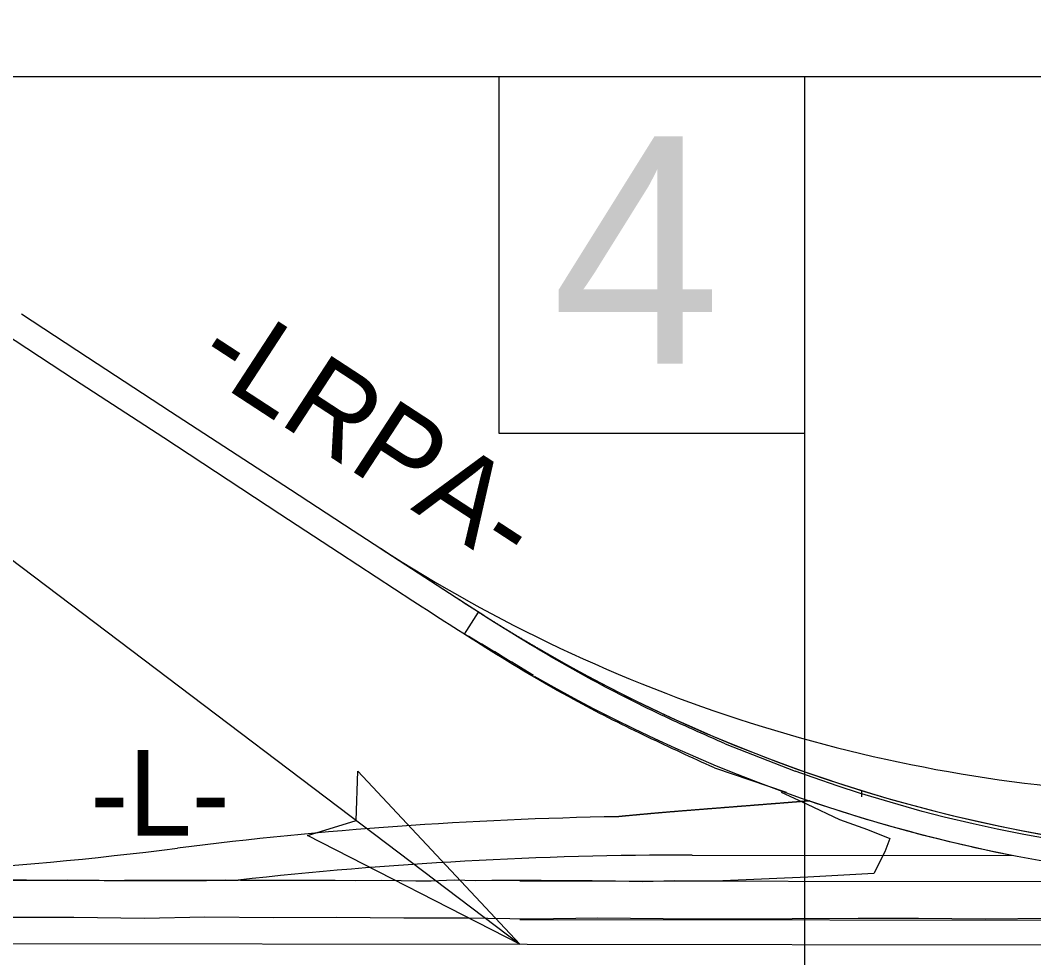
# Model space of a CAD drawing. Extents: x 2241278 to 2254132, y 649924 to 670434.
# Drawn here: x 2248087 to 2248712, y 663043 to 663620 of the extents above; entities that cross this region are included whole.
import ezdxf

# ---------------------------------------------------------------- set-up
doc = ezdxf.new("R2010")
doc.units = 0
for name, color, linetype in [('Pattern 4', 7, 'Continuous'), ('Prop DSN Text', 7, 'Continuous'), ('Prop Horizontal Alignment', 7, 'Continuous'), ('Prop RDY Alternate Text Yellow', 7, 'Continuous'), ('Prop Shade Heavy', 7, 'Continuous'), ('Prop Terminator CELL', 7, 'Continuous')]:
    doc.layers.add(name, color=color, linetype=linetype)

msp = doc.modelspace()

# ---------------------------------------------------------------- linework, layer by layer
at = {"layer": 'Pattern 4'}
for p, q in [((2248521.841407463, 663174.6436971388), (2248519.522645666, 663175.6435080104)), ((2248515.105036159, 663159.9058468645), (2248512.2885336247, 663161.0440069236)), ((2248515.105036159, 663159.9058468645), (2248559.4573341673, 663144.8071298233)), ((2248572.6726083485, 663092.3894687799), (2248520.317586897, 663090.174365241))]:
    msp.add_line(p, q, dxfattribs=at)
for points in [[(2248329.4042654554, 663262.4849119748), (2248284.103792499, 663292.0088999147), (2248247.485026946, 663316.0393573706), (2248175.8289858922, 663363.1105922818), (2248120.94965518, 663398.9078180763), (2248069.69245421, 663432.3596387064), (2248013.455276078, 663469.3554114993)], [(2248356.078308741, 663264.522525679), (2248292.577075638, 663305.7805350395), (2248253.8827733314, 663331.0648143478), (2248180.027896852, 663379.1161574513), (2248128.9810908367, 663412.5338641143), (2248088.157115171, 663439.3493886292)], [(2248521.841407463, 663174.6436971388), (2248565.005607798, 663157.6808520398)], [(2248721.7288937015, 663115.7938782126), (2248705.705206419, 663118.8617455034), (2248689.3392274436, 663122.0928519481), (2248674.518223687, 663125.3018916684), (2248656.802756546, 663129.4215805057), (2248643.099353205, 663133.0088348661), (2248623.461257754, 663138.6610662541), (2248604.4928478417, 663144.2158653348), (2248591.409358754, 663148.6315901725), (2248576.069985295, 663153.8869197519), (2248565.005607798, 663157.6808520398)], [(2248556.2431529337, 663144.7862920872), (2248572.2395090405, 663137.4677206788), (2248592.2424454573, 663128.0480086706), (2248609.576193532, 663121.8171947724), (2248623.3003326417, 663116.2153347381), (2248620.1638664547, 663108.031399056), (2248613.480428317, 663094.73850328), (2248572.6726083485, 663092.3894687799)], [(2248520.3169558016, 663090.1505896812), (2248504.1699949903, 663090.0648280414), (2248490.258087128, 663090.1531287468), (2248471.097404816, 663089.5668385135), (2248454.167620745, 663090.0858575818), (2248439.8441622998, 663090.1856504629), (2248424.9840950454, 663090.16302352), (2248408.3553073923, 663090.3644364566), (2248393.7272288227, 663090.4104906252), (2248377.930521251, 663090.3922780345), (2248367.899822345, 663090.2218880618), (2248354.894198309, 663090.6701577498), (2248340.5607366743, 663090.0924431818), (2248331.202885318, 663090.1106841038), (2248322.2477210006, 663090.1817673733), (2248310.2437386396, 663090.4806928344), (2248293.9882655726, 663090.1757451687), (2248281.4074375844, 663090.3535317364), (2248266.2599229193, 663090.4915979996), (2248254.554710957, 663090.4936267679), (2248239.906586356, 663090.3800321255), (2248223.15478609, 663090.4814798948), (2248213.939390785, 663090.5687101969), (2248202.102689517, 663090.479697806), (2248189.8201901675, 663090.3666204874), (2248177.578149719, 663090.4348081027), (2248162.4825770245, 663090.515426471), (2248151.6016491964, 663090.5274904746), (2248144.5116996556, 663090.3141685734), (2248135.989562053, 663090.5297860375), (2248128.1249061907, 663090.369108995), (2248116.7527300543, 663090.5500134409), (2248104.26732042, 663090.4141996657), (2248091.341284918, 663090.5368274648), (2248076.6107930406, 663090.6756517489)], [(2248081.0464070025, 663067.8691718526), (2248120.515788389, 663067.793861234), (2248163.942384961, 663067.1577460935), (2248201.1825565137, 663068.1425949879), (2248243.7835089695, 663067.6533045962), (2248282.20537548, 663067.7618854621), (2248323.7761026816, 663067.4963602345), (2248362.271043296, 663067.3567569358), (2248402.4895016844, 663066.8427278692), (2248443.2896640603, 663067.5144587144), (2248483.63697068, 663066.9709829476), (2248520.1972854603, 663066.8292124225), (2248562.9629134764, 663067.0011915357), (2248603.7788076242, 663067.1774478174), (2248640.827062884, 663067.1459457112), (2248681.9061098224, 663066.8638399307), (2248721.980150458, 663067.1694241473)]]:
    msp.add_lwpolyline(points, dxfattribs=at)
for points in [[(2248512.2885336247, 663161.0440069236), (2248471.59970113, 663180.0010341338), (2248428.6155889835, 663201.8366734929), (2248374.250741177, 663233.8227666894), (2248329.4042654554, 663262.4849119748)], [(2248519.522645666, 663175.6435080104), (2248479.68988319, 663193.7265774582), (2248434.573521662, 663216.8895753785), (2248382.2923462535, 663247.744846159), (2248356.078308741, 663264.522525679)]]:
    msp.add_spline(points, degree=3, dxfattribs=at)
at = {"layer": 'Prop DSN Text'}
for p, q in [((2251198.4216737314, 663585.5258229), (2247330.488405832, 663585.4218419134)), ((2248382.4794424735, 663365.7874708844), (2248382.479873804, 663585.4501224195)), ((2248570.7292612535, 663585.4551830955), (2248570.7574885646, 662535.4424933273)), ((2248570.7351665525, 663365.7871012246), (2248382.4794424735, 663365.7874708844)), ((2248361.085718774, 663242.2367312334), (2248369.7734972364, 663255.7572342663)), ((2248395.317459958, 663090.2059901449), (2248825.5682528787, 663089.6958861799))]:
    msp.add_line(p, q, dxfattribs=at)
msp.add_lwpolyline([(2249158.8155779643, 663065.3007723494), (2248395.289052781, 663066.2060069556)], dxfattribs=at)
for centre, radius, start, end in [((2248884.8876708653, 664051.8690549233), 948.0000000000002, 240.0836274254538, 267.63207033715), ((2248884.887670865, 664051.8690549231), 963.9999999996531, 240.08637361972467, 266.4720945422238)]:
    msp.add_arc(centre, radius, start, end, dxfattribs=at)
for points in [[(2248369.7734972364, 663255.7572342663), (2248370.8998162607, 663255.0369322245), (2248371.4631196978, 663254.677528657), (2248372.0266744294, 663254.3185233), (2248372.5904801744, 663253.9599163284), (2248373.154536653, 663253.601707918), (2248373.71884358, 663253.2438982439), (2248374.283400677, 663252.8864874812), (2248374.84820766, 663252.529475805), (2248375.413264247, 663252.1728633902), (2248375.978570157, 663251.8166504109), (2248376.544125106, 663251.4608370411), (2248377.109928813, 663251.1054234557), (2248377.675980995, 663250.7504098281), (2248378.2422813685, 663250.3957963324), (2248378.8088296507, 663250.0415831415), (2248379.3756255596, 663249.6877704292), (2248379.942668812, 663249.3343583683), (2248380.5099591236, 663248.9813471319), (2248381.077496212, 663248.6287368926), (2248381.6452797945, 663248.2765278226), (2248382.213309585, 663247.9247200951), (2248382.7815853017, 663247.5733138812), (2248383.350106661, 663247.2223093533), (2248383.918873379, 663246.871706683), (2248384.4878851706, 663246.521506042), (2248385.0571417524, 663246.171707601), (2248385.6266428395, 663245.8223115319), (2248386.1963881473, 663245.4733180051), (2248386.7663773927, 663245.1247271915), (2248387.3366102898, 663244.7765392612), (2248387.907086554, 663244.4287543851), (2248388.4778059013, 663244.0813727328), (2248389.0487680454, 663243.7343944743), (2248389.619972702, 663243.3878197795), (2248390.1914195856, 663243.0416488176), (2248390.7631084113, 663242.695881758), (2248391.335038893, 663242.3505187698), (2248391.907210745, 663242.0055600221), (2248392.479623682, 663241.6610056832), (2248393.052277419, 663241.3168559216), (2248393.6251716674, 663240.9731109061), (2248394.198306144, 663240.6297708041), (2248394.7716805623, 663240.2868357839), (2248395.345294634, 663239.9443060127), (2248395.9191480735, 663239.6021816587), (2248396.493240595, 663239.2604628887), (2248397.0675719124, 663238.9191498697), (2248397.642141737, 663238.5782427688), (2248398.216949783, 663238.2377417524), (2248398.791995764, 663237.8976469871), (2248399.3672793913, 663237.5579586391), (2248399.9428003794, 663237.2186768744), (2248400.5185584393, 663236.8798018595), (2248401.0945532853, 663236.5413337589), (2248401.670784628, 663236.2032727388), (2248402.247252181, 663235.8656189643), (2248402.8239556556, 663235.5283726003), (2248403.400894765, 663235.1915338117), (2248403.97806922, 663234.8551027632), (2248404.5554787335, 663234.519079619), (2248405.133123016, 663234.1834645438), (2248405.7110017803, 663233.8482577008), (2248406.289114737, 663233.5134592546), (2248406.867461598, 663233.1790693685), (2248407.4460420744, 663232.8450882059), (2248408.024855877, 663232.51151593), (2248408.6039027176, 663232.1783527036), (2248409.1831823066, 663231.8455986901), (2248409.7626943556, 663231.5132540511), (2248410.342438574, 663231.1813189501), (2248410.922414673, 663230.8497935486), (2248411.502622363, 663230.5186780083), (2248412.0830613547, 663230.1879724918)], [(2248403.624825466, 663216.6585334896), (2248403.6147998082, 663216.6632669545), (2248403.5848223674, 663216.6808397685), (2248361.085718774, 663242.2367312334)]]:
    msp.add_spline(points, degree=3, dxfattribs=at)
at = {"layer": 'Prop Horizontal Alignment'}
msp.add_line((2247428.233538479, 663052.3525343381), (2250137.966660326, 663049.1398834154), dxfattribs=at)
at = {"layer": 'Prop RDY Alternate Text Yellow'}
msp.add_line((2247642.6348494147, 663620.3536490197), (2248395.271298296, 663051.206017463), dxfattribs=at)
at = {"layer": 'Prop Shade Heavy'}
for p, q in [((2248605.912653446, 663141.9565136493), (2248605.9173879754, 663145.9565108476)), ((2248501.525676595, 663106.0800443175), (2248699.588879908, 663105.8456101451)), ((2248139.1278161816, 663090.4503854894), (2248139.128363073, 663090.5097271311))]:
    msp.add_line(p, q, dxfattribs=at)
for points in [[(2248369.7734972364, 663255.7572342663), (2248356.078308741, 663264.522525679), (2248309.2690039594, 663294.9354584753), (2248309.380721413, 663295.1012735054)], [(2247870.317827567, 663090.8271516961), (2247955.5535505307, 663090.7952202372), (2248023.034450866, 663090.5553697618), (2248139.1278161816, 663090.4503854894)], [(2248139.128363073, 663090.5097271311), (2248139.1278161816, 663090.4503854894), (2248189.8201901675, 663090.3666204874), (2248202.102689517, 663090.479697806), (2248221.6983625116, 663090.6270579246)]]:
    msp.add_lwpolyline(points, dxfattribs=at)
for centre, radius, start, end in [((2248824.332909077, 664091.0461487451), 947.9999999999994, 237.09835811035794, 267.63207033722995), ((2248884.8876708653, 664051.8690549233), 948.0000000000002, 240.0836274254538, 266.4430096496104), ((2248884.887670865, 664051.8690549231), 963.9999999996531, 251.17603514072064, 258.91770877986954), ((2248498.5807993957, 660618.0817890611), 2511.9999980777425, 90.97857068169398, 97.18442970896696), ((2247873.262704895, 665578.8254088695), 2487.9999999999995, 269.93218284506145, 277.1844297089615), ((2248498.5807993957, 660618.0817890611), 2487.999998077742, 89.93218284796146, 96.38951962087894)]:
    msp.add_arc(centre, radius, start, end, dxfattribs=at)
for points in [[(2248412.0830613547, 663230.1879724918), (2248411.502622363, 663230.5186780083), (2248410.922414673, 663230.8497935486), (2248410.342438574, 663231.1813189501), (2248409.7626943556, 663231.5132540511), (2248409.1831823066, 663231.8455986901), (2248408.6039027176, 663232.1783527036), (2248408.024855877, 663232.51151593), (2248407.4460420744, 663232.8450882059), (2248406.867461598, 663233.1790693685), (2248406.289114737, 663233.5134592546), (2248405.7110017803, 663233.8482577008), (2248405.133123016, 663234.1834645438), (2248404.5554787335, 663234.519079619), (2248403.97806922, 663234.8551027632), (2248403.400894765, 663235.1915338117), (2248402.8239556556, 663235.5283726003), (2248402.247252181, 663235.8656189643), (2248401.670784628, 663236.2032727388), (2248401.0945532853, 663236.5413337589), (2248400.5185584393, 663236.8798018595), (2248399.9428003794, 663237.2186768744), (2248399.3672793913, 663237.5579586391), (2248398.791995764, 663237.8976469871), (2248398.216949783, 663238.2377417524), (2248397.642141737, 663238.5782427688), (2248397.0675719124, 663238.9191498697), (2248396.493240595, 663239.2604628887), (2248395.9191480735, 663239.6021816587), (2248395.345294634, 663239.9443060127), (2248394.7716805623, 663240.2868357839), (2248394.198306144, 663240.6297708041), (2248393.6251716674, 663240.9731109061), (2248393.052277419, 663241.3168559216), (2248392.479623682, 663241.6610056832), (2248391.907210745, 663242.0055600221), (2248391.335038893, 663242.3505187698), (2248390.7631084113, 663242.695881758), (2248390.1914195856, 663243.0416488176), (2248389.619972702, 663243.3878197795), (2248389.0487680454, 663243.7343944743), (2248388.4778059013, 663244.0813727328), (2248387.907086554, 663244.4287543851), (2248387.3366102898, 663244.7765392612), (2248386.7663773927, 663245.1247271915), (2248386.1963881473, 663245.4733180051), (2248385.6266428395, 663245.8223115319), (2248385.0571417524, 663246.171707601), (2248384.4878851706, 663246.521506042), (2248383.918873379, 663246.871706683), (2248383.350106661, 663247.2223093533), (2248382.7815853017, 663247.5733138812), (2248382.213309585, 663247.9247200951), (2248381.6452797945, 663248.2765278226), (2248381.077496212, 663248.6287368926), (2248380.5099591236, 663248.9813471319), (2248379.942668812, 663249.3343583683), (2248379.3756255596, 663249.6877704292), (2248378.8088296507, 663250.0415831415), (2248378.2422813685, 663250.3957963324), (2248377.675980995, 663250.7504098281), (2248377.109928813, 663251.1054234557), (2248376.544125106, 663251.4608370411), (2248375.978570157, 663251.8166504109), (2248375.413264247, 663252.1728633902), (2248374.84820766, 663252.529475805), (2248374.283400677, 663252.8864874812), (2248373.71884358, 663253.2438982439), (2248373.154536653, 663253.601707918), (2248372.5904801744, 663253.9599163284), (2248372.0266744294, 663254.3185233), (2248371.4631196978, 663254.677528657), (2248370.8998162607, 663255.0369322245), (2248369.7734972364, 663255.7572342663)], [(2248555.906232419, 663138.015700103), (2248555.2304932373, 663137.9624458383), (2248554.554754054, 663137.9091915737), (2248553.879014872, 663137.8559373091), (2248553.2032756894, 663137.8026830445), (2248552.5275365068, 663137.7494287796), (2248551.8517973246, 663137.6961745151), (2248551.1760581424, 663137.6429202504), (2248550.5003189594, 663137.5896659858), (2248549.824579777, 663137.5364117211), (2248549.1488405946, 663137.4831574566), (2248548.473101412, 663137.429903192), (2248547.79736223, 663137.3766489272), (2248547.1216230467, 663137.3233946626), (2248546.4458838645, 663137.2701403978), (2248545.770144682, 663137.2168861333), (2248545.0944054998, 663137.1636318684), (2248544.418666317, 663137.1103776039), (2248543.7429271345, 663137.0571233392), (2248543.067187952, 663137.0038690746), (2248542.3914487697, 663136.95061481), (2248541.715709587, 663136.8973605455), (2248541.039970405, 663136.8441062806), (2248540.3642312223, 663136.7908520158), (2248539.688492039, 663136.7375977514), (2248539.012752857, 663136.6843434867), (2248538.3370136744, 663136.6310892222), (2248537.6612744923, 663136.5778349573), (2248536.9855353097, 663136.5245806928), (2248536.3097961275, 663136.471326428), (2248535.6340569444, 663136.4180721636), (2248534.958317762, 663136.3648178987), (2248534.28257858, 663136.3115636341), (2248533.6068393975, 663136.2583093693), (2248532.931100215, 663136.205055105), (2248532.2553610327, 663136.1518008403), (2248531.5796218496, 663136.0985465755), (2248530.903882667, 663136.045292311), (2248530.228143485, 663135.9920380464), (2248529.5524043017, 663135.938783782), (2248528.876665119, 663135.8855295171), (2248528.200925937, 663135.8322752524), (2248527.5251867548, 663135.7790209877), (2248526.8494475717, 663135.7257667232), (2248526.17370839, 663135.6725124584), (2248525.497969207, 663135.6192581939), (2248524.8222300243, 663135.5660039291), (2248524.146490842, 663135.5127496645), (2248523.47075166, 663135.4594953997), (2248522.795012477, 663135.4062411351), (2248522.1192732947, 663135.3529868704), (2248521.443534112, 663135.2997326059), (2248520.7677949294, 663135.2464783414), (2248520.0920557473, 663135.1932240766), (2248519.4163165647, 663135.139969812), (2248518.740577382, 663135.0867155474), (2248518.0648381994, 663135.0334612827), (2248517.3890990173, 663134.9802070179), (2248516.7133598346, 663134.9269527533), (2248516.0376206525, 663134.8736984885), (2248515.36188147, 663134.8204442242), (2248514.686142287, 663134.7671899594), (2248514.010403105, 663134.7139356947), (2248513.3346639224, 663134.6606814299), (2248512.65892474, 663134.6074271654), (2248511.983185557, 663134.5541729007), (2248511.3074463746, 663134.5009186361), (2248510.6317071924, 663134.4476643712), (2248509.95596801, 663134.3944101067), (2248509.280228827, 663134.3411558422), (2248508.604489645, 663134.2879015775), (2248507.928750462, 663134.2346473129), (2248507.2530112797, 663134.1813930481), (2248506.577272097, 663134.1281387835), (2248505.901532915, 663134.0748845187)], [(2248505.901532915, 663134.0748845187), (2248505.2257937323, 663134.0216302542), (2248504.5500545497, 663133.9683759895), (2248503.874315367, 663133.9151217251), (2248503.1985761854, 663133.8618674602), (2248502.5228370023, 663133.8086131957), (2248501.8470978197, 663133.755358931), (2248501.1689403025, 663133.7020773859), (2248500.489001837, 663133.6486309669), (2248499.8090924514, 663133.5950007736), (2248499.129212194, 663133.5411868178), (2248498.4493611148, 663133.4871891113), (2248497.7695392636, 663133.4330076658), (2248497.0897466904, 663133.3786424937), (2248496.4099834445, 663133.3240936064), (2248495.730249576, 663133.2693610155), (2248495.050545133, 663133.2144447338), (2248494.370870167, 663133.1593447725), (2248493.691224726, 663133.1040611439), (2248493.0116088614, 663133.0485938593), (2248492.3320226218, 663132.9929429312), (2248491.652466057, 663132.9371083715), (2248490.9729392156, 663132.8810901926), (2248490.2934421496, 663132.8248884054), (2248489.6139749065, 663132.7685030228), (2248488.934537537, 663132.7119340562), (2248488.2551300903, 663132.6551815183), (2248487.575752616, 663132.5982454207), (2248486.8964051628, 663132.5411257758), (2248486.2170877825, 663132.483822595), (2248485.5378005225, 663132.4263358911), (2248484.8585434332, 663132.3686656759), (2248484.1793165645, 663132.3108119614), (2248483.500119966, 663132.2527747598), (2248482.8209536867, 663132.1945540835), (2248482.141817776, 663132.1361499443), (2248481.462712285, 663132.0775623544), (2248480.783637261, 663132.0187913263), (2248480.1045927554, 663131.9598368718), (2248479.425578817, 663131.9006990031), (2248478.746595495, 663131.8413777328), (2248478.067642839, 663131.7818730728), (2248477.3887209, 663131.7221850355), (2248476.7098297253, 663131.6623136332), (2248476.030969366, 663131.6022588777), (2248475.3521398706, 663131.5420207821), (2248474.6733412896, 663131.4815993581), (2248473.994573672, 663131.4209946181), (2248473.315837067, 663131.3602065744), (2248472.637131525, 663131.2992352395), (2248471.9584570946, 663131.2380806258), (2248471.279813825, 663131.1767427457), (2248470.6012017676, 663131.1152216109), (2248469.9226209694, 663131.0535172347), (2248469.2440714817, 663130.9916296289), (2248468.565553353, 663130.9295588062), (2248467.887066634, 663130.8673047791), (2248467.2086113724, 663130.8048675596), (2248466.530187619, 663130.7422471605), (2248465.8517954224, 663130.6794435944), (2248465.1734348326, 663130.6164568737), (2248464.495105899, 663130.5532870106), (2248463.8168086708, 663130.489934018), (2248463.138543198, 663130.4263979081), (2248462.460309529, 663130.3626786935), (2248461.782107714, 663130.298776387), (2248461.103937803, 663130.2346910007), (2248460.425799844, 663130.1704225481), (2248459.7476938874, 663130.1059710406), (2248459.069619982, 663130.0413364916), (2248458.3915781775, 663129.9765189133), (2248457.713568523, 663129.9115183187), (2248457.035591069, 663129.84633472), (2248456.357645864, 663129.7809681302), (2248455.679732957, 663129.7154185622)]]:
    msp.add_spline(points, degree=3, dxfattribs=at)
msp.add_open_spline([(2248573.8418711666, 663139.429188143), (2248573.719731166, 663139.4195624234), (2248573.5975911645, 663139.4099367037), (2248573.475451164, 663139.400310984), (2248573.2502047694, 663139.3825595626), (2248573.0249583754, 663139.3648081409), (2248572.7997119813, 663139.3470567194), (2248572.5744655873, 663139.3293052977), (2248572.3492191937, 663139.3115538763), (2248572.123972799, 663139.2938024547), (2248571.898726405, 663139.2760510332), (2248571.673480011, 663139.2582996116), (2248571.448233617, 663139.24054819), (2248571.222987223, 663139.2227967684), (2248570.997740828, 663139.205045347), (2248570.772494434, 663139.1872939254), (2248570.54724804, 663139.1695425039), (2248570.322001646, 663139.1517910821), (2248570.0967552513, 663139.1340396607), (2248569.8715088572, 663139.1162882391), (2248569.646262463, 663139.0985368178), (2248569.421016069, 663139.0807853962), (2248569.1957696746, 663139.0630339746), (2248568.970523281, 663139.0452825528), (2248568.745276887, 663139.0275311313), (2248568.520030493, 663139.0097797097), (2248568.294784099, 663138.9920282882), (2248568.069537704, 663138.9742768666), (2248567.84429131, 663138.9565254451), (2248567.619044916, 663138.9387740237), (2248567.3937985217, 663138.9210226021), (2248567.168552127, 663138.9032711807), (2248566.943305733, 663138.8855197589), (2248566.718059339, 663138.8677683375), (2248566.492812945, 663138.850016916), (2248566.267566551, 663138.8322654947), (2248566.042320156, 663138.8145140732), (2248565.8170737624, 663138.7967626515), (2248565.5918273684, 663138.7790112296), (2248565.366580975, 663138.7612598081), (2248565.14133458, 663138.7435083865), (2248564.9160881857, 663138.7257569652), (2248564.6908417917, 663138.7080055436), (2248564.4655953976, 663138.690254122), (2248564.2403490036, 663138.6725027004), (2248564.015102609, 663138.6547512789), (2248563.789856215, 663138.6369998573), (2248563.564609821, 663138.6192484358), (2248563.339363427, 663138.6014970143), (2248563.1141170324, 663138.5837455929), (2248562.8888706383, 663138.5659941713), (2248562.6636242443, 663138.5482427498), (2248562.43837785, 663138.530491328), (2248562.213131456, 663138.5127399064), (2248561.9878850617, 663138.4949884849), (2248561.7626386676, 663138.4772370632), (2248561.5373922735, 663138.4594856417), (2248561.31214588, 663138.4417342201), (2248561.086899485, 663138.4239827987), (2248560.861653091, 663138.4062313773), (2248560.636406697, 663138.3884799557), (2248560.411160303, 663138.3707285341), (2248560.1859139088, 663138.3529771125), (2248559.9606675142, 663138.335225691), (2248559.73542112, 663138.3174742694), (2248559.510174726, 663138.2997228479), (2248559.2849283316, 663138.2819714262), (2248559.059681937, 663138.2642200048), (2248558.8344355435, 663138.2464685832), (2248558.6091891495, 663138.2287171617), (2248558.3839427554, 663138.2109657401), (2248558.158696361, 663138.1932143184), (2248557.933449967, 663138.1754628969), (2248557.708203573, 663138.1577114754), (2248557.4829571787, 663138.139960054), (2248557.257710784, 663138.1222086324), (2248557.0324643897, 663138.1044572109), (2248556.8072179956, 663138.0867057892), (2248556.581971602, 663138.0689543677), (2248556.3567252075, 663138.0512029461), (2248556.131478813, 663138.0334515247), (2248555.906232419, 663138.015700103)], degree=3, dxfattribs=at)
at = {"layer": 'Prop Terminator CELL'}
msp.add_lwpolyline([(2248295.3727455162, 663157.8424050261), (2248395.271298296, 663051.206017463), (2248264.335239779, 663118.1249877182), (2248294.452381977, 663127.4458109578)], close=True, dxfattribs=at)

# ---------------------------------------------------------------- texts
at = {"layer": 'Prop RDY Alternate Text Yellow'}
for s, height, p in [('4', 140.00456250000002, (2248414.9721824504, 663408.8894674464)), ('-L-', 52.59375, (2248130.5730082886, 663118.1316009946))]:
    msp.add_text(s, height=height, dxfattribs=at).set_placement(p)
msp.add_text('-LRPA-', height=52.59375, rotation=326.8849793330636, dxfattribs=at).set_placement((2248193.3071238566, 663406.8245869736))

doc.saveas('drawing.dxf')
